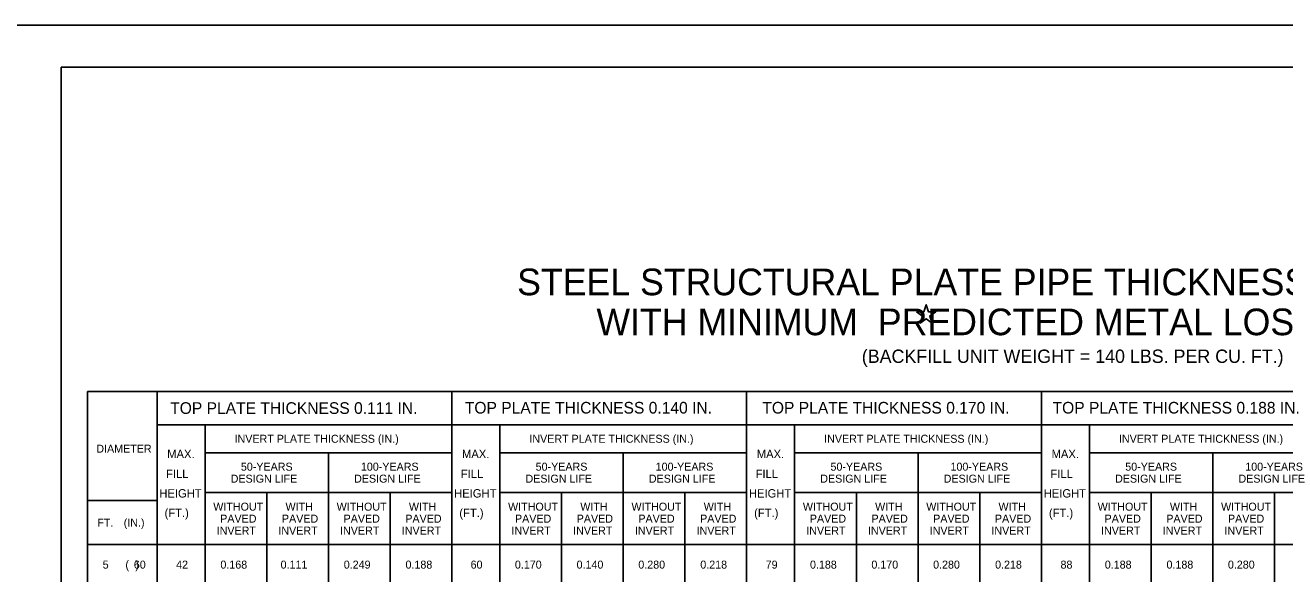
# Model space of a CAD drawing. Extents: x 591 to 2288, y -189 to 2187.
# Drawn here: x 1459.5 to 1910.5, y 1990.5 to 2187.2 of the extents above; entities that cross this region are included whole.
import ezdxf

# ---------------------------------------------------------------- set-up
doc = ezdxf.new("R2010")
doc.units = 0
for name, color, linetype in [('1', 7, 'Continuous'), ('2', 7, 'Continuous'), ('PLT-BNDY', 7, 'Continuous')]:
    doc.layers.add(name, color=color, linetype=linetype)

msp = doc.modelspace()

# ---------------------------------------------------------------- linework, layer by layer
at = {"layer": '1'}
for p, q in [((1481.73, 2055.84), (1481.73, 1772.38)), ((1481.73, 2055.84), (2245.62, 2055.84)), ((1506.68, 2055.84), (1506.68, 1772.38)), ((1612.25, 2055.84), (1612.25, 1772.38)), ((1717.82, 2055.84), (1717.82, 1772.38)), ((1823.39, 2055.84), (1823.39, 1772.38)), ((1506.68, 2043.97), (1612.25, 2043.97)), ((1523.87, 2043.97), (1523.87, 1772.38)), ((1612.25, 2043.97), (1717.82, 2043.97)), ((1629.44, 2043.97), (1629.44, 1772.38)), ((1717.82, 2043.97), (1823.39, 2043.97)), ((1735.01, 2043.97), (1735.01, 1772.38)), ((1823.39, 2043.97), (1928.97, 2043.97)), ((1840.58, 2043.97), (1840.58, 1772.38)), ((1523.87, 2033.93), (1612.25, 2033.93)), ((1568.06, 2033.93), (1568.06, 1772.38)), ((1629.44, 2033.93), (1717.82, 2033.93)), ((1673.63, 2033.93), (1673.63, 1772.38)), ((1735.01, 2033.93), (1823.39, 2033.93)), ((1779.2, 2033.93), (1779.2, 1772.38)), ((1840.58, 2033.93), (1928.97, 2033.93)), ((1884.77, 2033.93), (1884.77, 1772.38)), ((1506.68, 2016.74), (1481.73, 2016.74)), ((1523.87, 2019.6), (1568.06, 2019.6)), ((1545.96, 2019.6), (1545.96, 1772.38)), ((1612.25, 2019.6), (1568.06, 2019.6)), ((1590.16, 2019.6), (1590.16, 1772.38)), ((1629.44, 2019.6), (1673.63, 2019.6)), ((1651.53, 2019.6), (1651.53, 1772.38)), ((1717.82, 2019.6), (1673.63, 2019.6)), ((1695.73, 2019.6), (1695.73, 1772.38)), ((1735.01, 2019.6), (1779.2, 2019.6)), ((1757.1, 2019.6), (1757.1, 1772.38)), ((1823.39, 2019.6), (1779.2, 2019.6)), ((1801.3, 2019.6), (1801.3, 1772.38)), ((1840.58, 2019.6), (1884.77, 2019.6)), ((1862.68, 2019.6), (1862.68, 1772.38)), ((1928.97, 2019.6), (1884.77, 2019.6)), ((1906.87, 2019.6), (1906.87, 1772.38)), ((2245.68, 2000.97), (1481.73, 2000.97))]:
    msp.add_line(p, q, dxfattribs=at)
at = {"layer": '2'}
for p, q in [((1472.34, 1608.21), (1472.34, 2172.21)), ((1472.34, 2172.21), (2258.34, 2172.21)), ((1782.12, 2083.35), (1782.12, 2083.35))]:
    msp.add_line(p, q, dxfattribs=at)
msp.add_lwpolyline([(1778.67, 2084.47), (1781.31, 2084.45), (1782.12, 2086.97), (1782.92, 2084.44), (1785.57, 2084.47), (1783.41, 2082.9), (1784.26, 2080.41), (1782.1, 2081.96), (1779.99, 2080.41), (1780.81, 2082.92), (1778.67, 2084.47)], dxfattribs=at)
at = {"layer": 'PLT-BNDY'}
msp.add_lwpolyline([(1432.34, 2187.21), (2273.34, 2187.21), (2273.34, 1593.21), (1432.34, 1593.21)], close=True, dxfattribs=at)

# ---------------------------------------------------------------- texts
at = {"layer": '1'}
for s, height, p in [('STEEL STRUCTURAL PLATE PIPE THICKNESS REQUIREMENTS', 9.5546, (1635.62, 2090.38)), ('WITH MINIMUM  PREDICTED METAL LOSS CONDITION', 9.5546, (1664.02, 2076.05)), ('(BACKFILL UNIT WEIGHT = 140 LBS. PER CU. FT.)', 4.7773, (1759.05, 2066.12)), ('TOP PLATE THICKNESS 0.111 IN.', 4.1801, (1511.38, 2047.84)), ('TOP PLATE THICKNESS 0.140 IN.', 4.1801, (1616.89, 2047.96)), ('TOP PLATE THICKNESS 0.170 IN.', 4.1801, (1723.43, 2047.96)), ('TOP PLATE THICKNESS 0.188 IN.', 4.1801, (1827.37, 2047.96)), ('INVERT PLATE THICKNESS (IN.)', 2.8664, (1534.44, 2037.49)), ('INVERT PLATE THICKNESS (IN.)', 2.8664, (1640.01, 2037.49)), ('INVERT PLATE THICKNESS (IN.)', 2.8664, (1745.58, 2037.49)), ('INVERT PLATE THICKNESS (IN.)', 2.8664, (1851.15, 2037.49)), ('DIAMETER', 2.866, (1484.93, 2033.93)), ('50-YEARS', 2.866, (1536.69, 2027.48)), ('100-YEARS', 2.866, (1579.67, 2027.48)), ('50-YEARS', 2.866, (1642.26, 2027.48)), ('100-YEARS', 2.866, (1685.24, 2027.48)), ('50-YEARS', 2.866, (1747.84, 2027.48)), ('100-YEARS', 2.866, (1790.81, 2027.48)), ('50-YEARS', 2.866, (1853.41, 2027.48)), ('100-YEARS', 2.866, (1896.38, 2027.48)), ('DESIGN LIFE', 2.8664, (1533.04, 2023.19)), ('DESIGN LIFE', 2.8664, (1577.23, 2023.19)), ('DESIGN LIFE', 2.8664, (1638.61, 2023.19)), ('DESIGN LIFE', 2.8664, (1682.8, 2023.19)), ('DESIGN LIFE', 2.8664, (1744.18, 2023.19)), ('DESIGN LIFE', 2.8664, (1788.37, 2023.19)), ('DESIGN LIFE', 2.8664, (1849.75, 2023.19)), ('DESIGN LIFE', 2.8664, (1893.94, 2023.19)), ('WITHOUT', 2.866, (1526.81, 2013.15)), ('WITH', 2.866, (1552.68, 2013.15)), ('WITHOUT', 2.866, (1571, 2013.15)), ('WITH', 2.866, (1596.87, 2013.15)), ('WITHOUT', 2.866, (1632.38, 2013.15)), ('WITH', 2.866, (1658.24, 2013.15)), ('WITHOUT', 2.866, (1676.57, 2013.15)), ('WITH', 2.866, (1702.44, 2013.15)), ('WITHOUT', 2.866, (1737.95, 2013.15)), ('WITH', 2.866, (1763.82, 2013.15)), ('WITHOUT', 2.866, (1782.14, 2013.15)), ('WITH', 2.866, (1808.01, 2013.15)), ('WITHOUT', 2.866, (1843.52, 2013.15)), ('WITH', 2.866, (1869.39, 2013.15)), ('WITHOUT', 2.866, (1887.71, 2013.15)), ('FT.', 2.866, (1485.29, 2007.42)), ('(IN.)', 2.866, (1494.74, 2007.42)), ('INVERT', 2.866, (1528.03, 2004.56)), ('PAVED', 2.866, (1529.29, 2008.85)), ('INVERT', 2.866, (1550.12, 2004.56)), ('PAVED', 2.866, (1551.39, 2008.85)), ('INVERT', 2.866, (1572.22, 2004.56)), ('PAVED', 2.866, (1573.48, 2008.85)), ('INVERT', 2.866, (1594.32, 2004.56)), ('PAVED', 2.866, (1595.58, 2008.85)), ('INVERT', 2.866, (1633.6, 2004.56)), ('PAVED', 2.866, (1634.86, 2008.85)), ('INVERT', 2.866, (1655.69, 2004.56)), ('PAVED', 2.866, (1656.96, 2008.85)), ('INVERT', 2.866, (1677.79, 2004.56)), ('PAVED', 2.866, (1679.05, 2008.85)), ('INVERT', 2.866, (1699.89, 2004.56)), ('PAVED', 2.866, (1701.15, 2008.85)), ('INVERT', 2.866, (1739.17, 2004.56)), ('PAVED', 2.866, (1740.43, 2008.85)), ('INVERT', 2.866, (1761.26, 2004.56)), ('PAVED', 2.866, (1762.53, 2008.85)), ('INVERT', 2.866, (1783.36, 2004.56)), ('PAVED', 2.866, (1784.62, 2008.85)), ('INVERT', 2.866, (1805.46, 2004.56)), ('PAVED', 2.866, (1806.72, 2008.85)), ('INVERT', 2.866, (1844.74, 2004.56)), ('PAVED', 2.866, (1846, 2008.85)), ('INVERT', 2.866, (1866.83, 2004.56)), ('PAVED', 2.866, (1868.1, 2008.85)), ('INVERT', 2.866, (1888.93, 2004.56)), ('PAVED', 2.866, (1890.19, 2008.85)), ('5', 2.87, (1487.21, 1992.37)), ('(  )', 2.986, (1495.33, 1992.34)), ('60', 2.866, (1498.36, 1992.37)), ('42', 2.866, (1513.51, 1992.37)), ('0.168', 2.866, (1529.36, 1992.37)), ('0.111', 2.866, (1550.92, 1992.37)), ('0.249', 2.866, (1573.54, 1992.37)), ('0.188', 2.866, (1595.65, 1992.37)), ('60', 2.866, (1618.97, 1992.37)), ('0.170', 2.866, (1634.82, 1992.37)), ('0.140', 2.866, (1656.92, 1992.37)), ('0.280', 2.866, (1679.02, 1992.37)), ('0.218', 2.866, (1701.22, 1992.37)), ('79', 2.866, (1724.64, 1992.37)), ('0.188', 2.866, (1740.5, 1992.37)), ('0.170', 2.866, (1762.49, 1992.37)), ('0.280', 2.866, (1784.59, 1992.37)), ('0.218', 2.866, (1806.79, 1992.37)), ('88', 2.866, (1830.22, 1992.37)), ('0.188', 2.866, (1846.07, 1992.37)), ('0.188', 2.866, (1868.17, 1992.37)), ('0.280', 2.866, (1890.16, 1992.37))]:
    msp.add_text(s, height=height, dxfattribs=at).set_placement(p)
at = {"layer": '2'}
for s, p in [('MAX.', (1510.31, 2031.97)), ('MAX.', (1615.88, 2031.97)), ('MAX.', (1721.45, 2031.97)), ('MAX.', (1827.02, 2031.97)), ('FILL', (1509.89, 2024.85)), ('FILL', (1615.46, 2024.85)), ('FILL', (1721.03, 2024.85)), ('FILL', (1826.6, 2024.85)), ('HEIGHT', (1507.49, 2017.85)), ('HEIGHT', (1613.06, 2017.85)), ('HEIGHT', (1718.63, 2017.85)), ('HEIGHT', (1824.21, 2017.85)), ('(FT.)', (1509.36, 2010.85)), ('(FT.)', (1614.93, 2010.85)), ('(FT.)', (1720.5, 2010.85)), ('(FT.)', (1826.07, 2010.85))]:
    msp.add_text(s, height=3, dxfattribs=at).set_placement(p)

doc.saveas('drawing.dxf')
